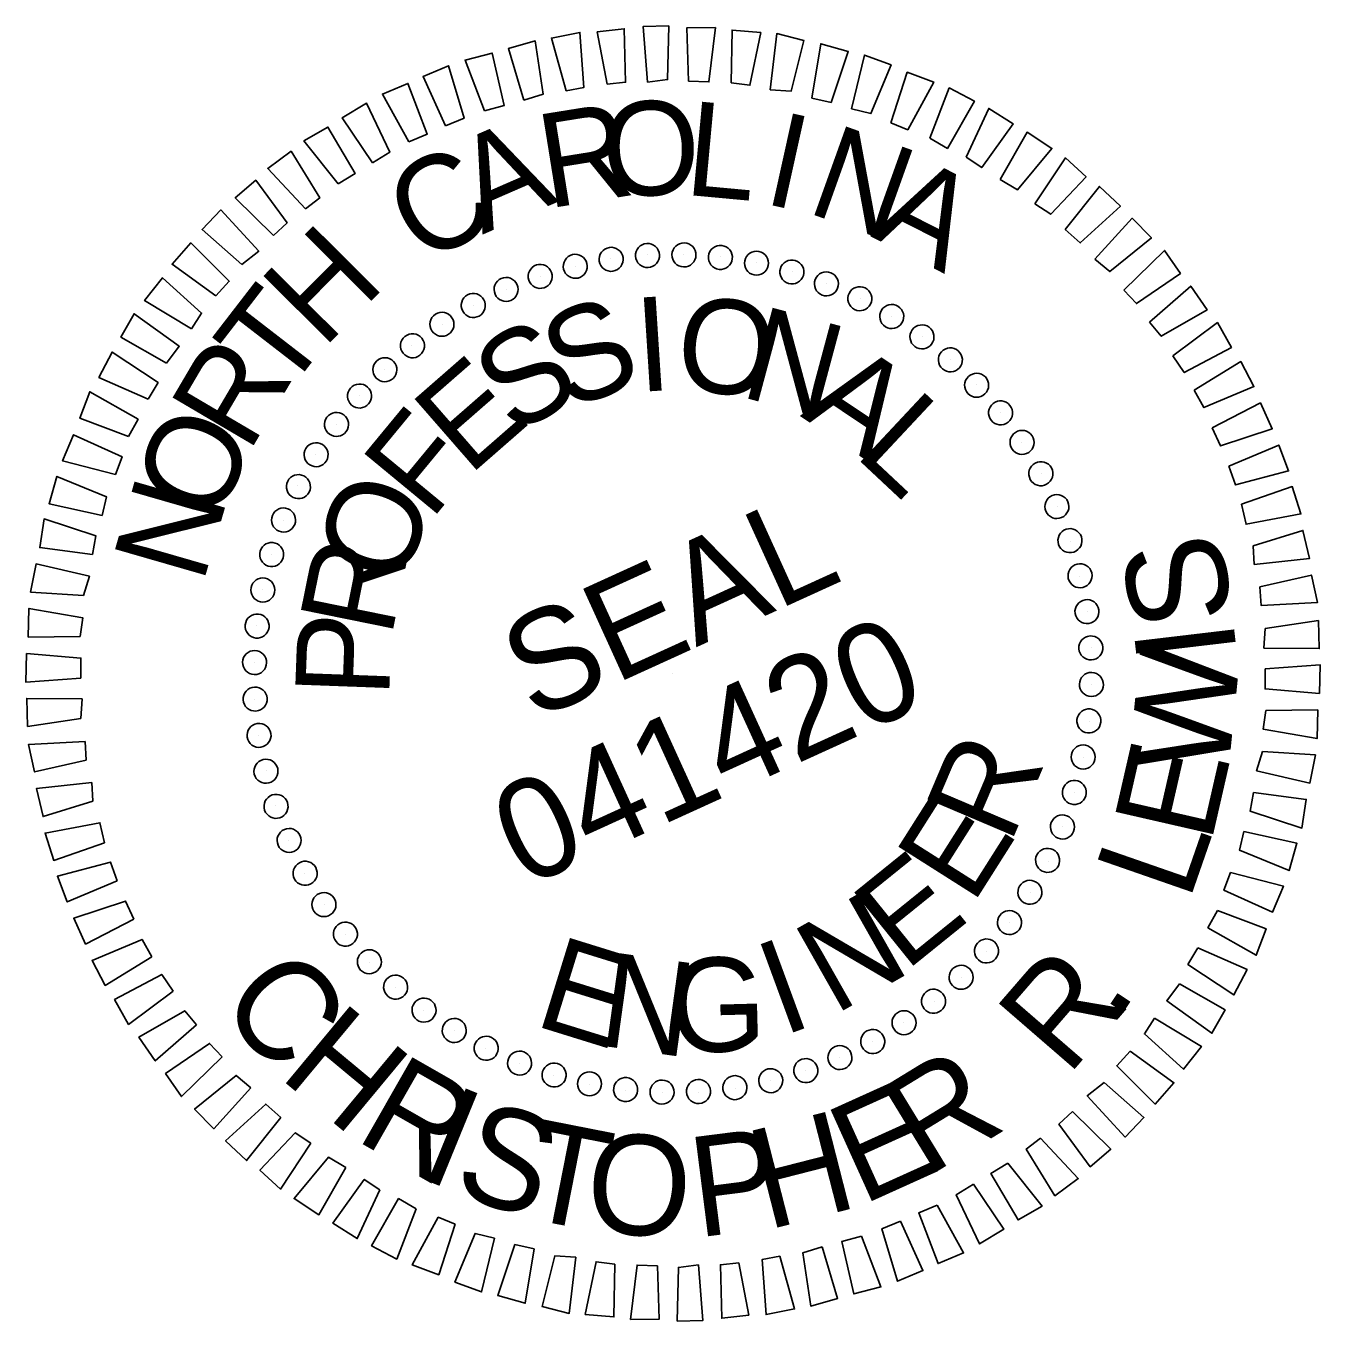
# Model space of a CAD drawing. Extents: x 2246788 to 2248774, y 662010 to 663780.
# Drawn here: x 2248637.9 to 2248715.4, y 663702.5 to 663780.1 of the extents above; entities that cross this region are included whole.
import ezdxf

# ---------------------------------------------------------------- set-up
doc = ezdxf.new("R2010")
doc.units = 0
doc.layers.add('Sheet PE Seal Cell', color=7, linetype='Continuous')

msp = doc.modelspace()

# ---------------------------------------------------------------- linework, layer by layer
at = {"layer": 'Sheet PE Seal Cell'}
for p, q in [((2248675.104, 663766.359), (2248675.104, 663766.359)), ((2248677.297, 663766.369), (2248677.297, 663766.369)), ((2248679.486, 663766.268), (2248679.486, 663766.268)), ((2248670.805, 663765.664), (2248670.805, 663765.664)), ((2248672.903, 663766.125), (2248672.903, 663766.125)), ((2248681.643, 663765.877), (2248681.643, 663765.877)), ((2248668.704, 663765.091), (2248668.704, 663765.091)), ((2248683.795, 663765.374), (2248683.795, 663765.374)), ((2248685.827, 663764.652), (2248685.827, 663764.652)), ((2248666.64, 663764.315), (2248666.64, 663764.315)), ((2248664.658, 663763.357), (2248664.658, 663763.357)), ((2248687.876, 663763.772), (2248687.876, 663763.772)), ((2248689.74, 663762.698), (2248689.74, 663762.698)), ((2248662.826, 663762.193), (2248662.826, 663762.193)), ((2248660.99, 663760.916), (2248660.99, 663760.916)), ((2248691.574, 663761.446), (2248691.574, 663761.446)), ((2248693.292, 663760.086), (2248693.292, 663760.086)), ((2248659.328, 663759.5), (2248659.328, 663759.5)), ((2248694.85, 663758.598), (2248694.85, 663758.598)), ((2248657.84, 663757.942), (2248657.84, 663757.942)), ((2248696.267, 663756.936), (2248696.267, 663756.936)), ((2248656.48, 663756.224), (2248656.48, 663756.224)), ((2248697.543, 663755.1), (2248697.543, 663755.1)), ((2248655.228, 663754.39), (2248655.228, 663754.39)), ((2248698.707, 663753.268), (2248698.707, 663753.268)), ((2248654.154, 663752.526), (2248654.154, 663752.526)), ((2248699.665, 663751.286), (2248699.665, 663751.286)), ((2248653.274, 663750.477), (2248653.274, 663750.477)), ((2248700.441, 663749.222), (2248700.441, 663749.222)), ((2248652.552, 663748.445), (2248652.552, 663748.445)), ((2248701.014, 663747.121), (2248701.014, 663747.121)), ((2248652.049, 663746.293), (2248652.049, 663746.293)), ((2248701.475, 663745.023), (2248701.475, 663745.023)), ((2248651.658, 663744.136), (2248651.658, 663744.136)), ((2248701.709, 663742.822), (2248701.709, 663742.822)), ((2248651.557, 663741.947), (2248651.557, 663741.947)), ((2248676.638, 663741.288), (2248676.638, 663741.288)), ((2248701.719, 663740.629), (2248701.719, 663740.629)), ((2248651.567, 663739.754), (2248651.567, 663739.754)), ((2248701.618, 663738.44), (2248701.618, 663738.44)), ((2248651.801, 663737.553), (2248651.801, 663737.553)), ((2248701.227, 663736.283), (2248701.227, 663736.283)), ((2248652.262, 663735.455), (2248652.262, 663735.455)), ((2248700.724, 663734.131), (2248700.724, 663734.131)), ((2248652.835, 663733.354), (2248652.835, 663733.354)), ((2248700.002, 663732.099), (2248700.002, 663732.099)), ((2248653.611, 663731.289), (2248653.611, 663731.289)), ((2248699.122, 663730.05), (2248699.122, 663730.05)), ((2248654.569, 663729.308), (2248654.569, 663729.308)), ((2248698.048, 663728.186), (2248698.048, 663728.186)), ((2248655.733, 663727.476), (2248655.733, 663727.476)), ((2248696.796, 663726.352), (2248696.796, 663726.352)), ((2248657.01, 663725.64), (2248657.01, 663725.64)), ((2248695.436, 663724.634), (2248695.436, 663724.634)), ((2248658.426, 663723.978), (2248658.426, 663723.978)), ((2248693.948, 663723.076), (2248693.948, 663723.076)), ((2248659.984, 663722.49), (2248659.984, 663722.49)), ((2248692.286, 663721.659), (2248692.286, 663721.659)), ((2248661.702, 663721.13), (2248661.702, 663721.13)), ((2248663.537, 663719.878), (2248663.537, 663719.878)), ((2248690.45, 663720.383), (2248690.45, 663720.383)), ((2248688.618, 663719.219), (2248688.618, 663719.219)), ((2248665.4, 663718.804), (2248665.4, 663718.804)), ((2248686.637, 663718.261), (2248686.637, 663718.261)), ((2248667.449, 663717.924), (2248667.449, 663717.924)), ((2248684.572, 663717.485), (2248684.572, 663717.485)), ((2248669.481, 663717.202), (2248669.481, 663717.202)), ((2248671.634, 663716.699), (2248671.634, 663716.699)), ((2248682.471, 663716.912), (2248682.471, 663716.912)), ((2248673.79, 663716.308), (2248673.79, 663716.308)), ((2248675.979, 663716.207), (2248675.979, 663716.207)), ((2248678.172, 663716.217), (2248678.172, 663716.217)), ((2248680.373, 663716.451), (2248680.373, 663716.451))]:
    msp.add_line(p, q, dxfattribs=at)
for points in [[(2248670.245, 663776.178), (2248669.352, 663779.343), (2248671.065, 663779.684), (2248671.304, 663776.386)], [(2248672.699, 663776.582), (2248672.096, 663779.714), (2248673.713, 663779.901), (2248673.799, 663776.699)], [(2248675.119, 663776.696), (2248674.859, 663780.039), (2248676.382, 663780.074), (2248676.311, 663776.854)], [(2248677.561, 663776.764), (2248677.475, 663779.967), (2248679.175, 663779.973), (2248678.79, 663776.72)], [(2248680.13, 663776.671), (2248680.177, 663779.825), (2248681.894, 663779.673), (2248681.244, 663776.519)], [(2248682.465, 663776.252), (2248682.855, 663779.616), (2248684.473, 663779.2), (2248683.714, 663776.162)], [(2248667.697, 663775.621), (2248666.779, 663778.72), (2248668.384, 663779.176), (2248668.851, 663775.982)], [(2248684.952, 663775.737), (2248685.495, 663779.006), (2248687.134, 663778.544), (2248686.107, 663775.494)], [(2248665.347, 663774.99), (2248664.181, 663778.03), (2248665.807, 663778.441), (2248666.522, 663775.305)], [(2248687.324, 663775.114), (2248688.111, 663778.33), (2248689.701, 663777.736), (2248688.499, 663774.825)], [(2248663.01, 663774.09), (2248661.662, 663777.047), (2248663.184, 663777.686), (2248664.122, 663774.542)], [(2248689.687, 663774.268), (2248690.669, 663777.298), (2248692.259, 663776.704), (2248690.702, 663773.851)], [(2248660.805, 663773.14), (2248659.23, 663775.994), (2248660.752, 663776.632), (2248661.918, 663773.592)], [(2248692.026, 663773.356), (2248693.186, 663776.357), (2248694.701, 663775.564), (2248693.078, 663772.736)], [(2248658.634, 663771.876), (2248656.806, 663774.56), (2248658.27, 663775.447), (2248659.663, 663772.51)], [(2248694.2, 663772.203), (2248695.558, 663775.13), (2248697.024, 663774.205), (2248695.14, 663771.588)], [(2248656.574, 663770.608), (2248654.519, 663773.188), (2248655.958, 663774.009), (2248657.604, 663771.242)], [(2248696.233, 663770.877), (2248697.856, 663773.705), (2248699.343, 663772.734), (2248697.284, 663770.257)], [(2248654.618, 663769.112), (2248652.357, 663771.543), (2248653.758, 663772.566), (2248655.47, 663769.775)], [(2248698.328, 663769.414), (2248700.15, 663772.167), (2248701.384, 663771.027), (2248699.268, 663768.798)], [(2248652.704, 663767.525), (2248650.413, 663769.778), (2248651.637, 663770.831), (2248653.514, 663768.279)], [(2248700.129, 663767.872), (2248702.192, 663770.46), (2248703.447, 663769.274), (2248701.041, 663767.079)], [(2248650.806, 663765.781), (2248648.421, 663767.881), (2248649.537, 663769.049), (2248651.819, 663766.573)], [(2248701.923, 663766.107), (2248704.159, 663768.555), (2248705.302, 663767.372), (2248702.813, 663765.359)], [(2248649.24, 663763.914), (2248646.623, 663765.798), (2248647.743, 663767.078), (2248650.054, 663764.779)], [(2248703.646, 663764.255), (2248706.081, 663766.628), (2248707.038, 663765.251), (2248704.4, 663763.444)], [(2248647.781, 663761.93), (2248644.978, 663763.62), (2248646.056, 663764.991), (2248648.396, 663762.87)], [(2248705.187, 663762.32), (2248707.66, 663764.49), (2248708.638, 663763.068), (2248705.896, 663761.488)], [(2248646.297, 663759.881), (2248643.556, 663761.434), (2248644.345, 663762.837), (2248647.049, 663760.883)], [(2248706.592, 663760.322), (2248709.259, 663762.307), (2248710.1, 663760.822), (2248707.271, 663759.313)], [(2248645.19, 663757.728), (2248642.238, 663759.02), (2248643.032, 663760.535), (2248645.785, 663758.713)], [(2248707.86, 663758.263), (2248710.652, 663759.974), (2248711.448, 663758.469), (2248708.449, 663757.212)], [(2248644.013, 663755.488), (2248641.099, 663756.578), (2248641.693, 663758.167), (2248644.587, 663756.519)], [(2248708.942, 663756.008), (2248711.837, 663757.493), (2248712.542, 663755.946), (2248709.44, 663754.916)], [(2248643.237, 663753.211), (2248640.067, 663754.019), (2248640.727, 663755.584), (2248643.633, 663754.271)], [(2248709.933, 663753.713), (2248712.932, 663754.969), (2248713.525, 663753.426), (2248710.34, 663752.579)], [(2248642.432, 663750.757), (2248639.258, 663751.453), (2248639.72, 663753.092), (2248642.696, 663751.866)], [(2248710.701, 663751.425), (2248713.737, 663752.479), (2248714.26, 663750.849), (2248710.971, 663750.23)], [(2248641.855, 663748.406), (2248638.693, 663748.833), (2248638.957, 663750.546), (2248642.053, 663749.54)], [(2248711.394, 663748.939), (2248714.381, 663749.86), (2248714.768, 663748.168), (2248711.466, 663747.818)], [(2248641.32, 663745.964), (2248638.15, 663746.168), (2248638.479, 663747.856), (2248641.674, 663747.114)], [(2248711.798, 663746.485), (2248714.889, 663747.179), (2248715.254, 663745.533), (2248711.87, 663745.364)], [(2248641.119, 663743.51), (2248638.007, 663743.465), (2248638.047, 663745.187), (2248641.271, 663744.623)], [(2248712.111, 663743.99), (2248715.305, 663744.457), (2248715.356, 663742.777), (2248712.046, 663742.807)], [(2248641.163, 663741.002), (2248637.865, 663740.763), (2248637.905, 663742.485), (2248641.162, 663742.21)], [(2248712.113, 663741.574), (2248715.411, 663741.813), (2248715.371, 663740.091), (2248712.114, 663740.366)], [(2248641.165, 663738.586), (2248637.971, 663738.119), (2248637.92, 663739.799), (2248641.23, 663739.769)], [(2248712.157, 663739.066), (2248715.269, 663739.111), (2248715.229, 663737.389), (2248712.005, 663737.953)], [(2248641.478, 663736.091), (2248638.388, 663735.397), (2248638.022, 663737.043), (2248641.407, 663737.212)], [(2248711.956, 663736.612), (2248715.126, 663736.408), (2248714.797, 663734.72), (2248711.602, 663735.461)], [(2248641.882, 663733.637), (2248638.895, 663732.716), (2248638.508, 663734.408), (2248641.81, 663734.758)], [(2248711.421, 663734.17), (2248714.583, 663733.743), (2248714.319, 663732.029), (2248711.223, 663733.036)], [(2248642.575, 663731.151), (2248639.539, 663730.097), (2248639.016, 663731.727), (2248642.305, 663732.346)], [(2248710.844, 663731.819), (2248714.018, 663731.123), (2248713.556, 663729.484), (2248710.58, 663730.71)], [(2248643.343, 663728.863), (2248640.344, 663727.607), (2248639.751, 663729.149), (2248642.936, 663729.997)], [(2248710.039, 663729.365), (2248713.21, 663728.557), (2248712.549, 663726.992), (2248709.643, 663728.305)], [(2248644.334, 663726.568), (2248641.439, 663725.083), (2248640.734, 663726.63), (2248643.836, 663727.66)], [(2248709.263, 663727.088), (2248712.177, 663725.998), (2248711.583, 663724.409), (2248708.689, 663726.057)], [(2248645.416, 663724.313), (2248642.625, 663722.602), (2248641.829, 663724.107), (2248644.827, 663725.364)], [(2248708.086, 663724.848), (2248711.038, 663723.556), (2248710.245, 663722.041), (2248707.491, 663723.863)], [(2248646.684, 663722.254), (2248644.017, 663720.269), (2248643.176, 663721.754), (2248646.005, 663723.263)], [(2248706.979, 663722.695), (2248709.72, 663721.142), (2248708.931, 663719.739), (2248706.227, 663721.693)], [(2248648.089, 663720.256), (2248645.616, 663718.086), (2248644.639, 663719.508), (2248647.381, 663721.088)], [(2248705.495, 663720.646), (2248708.298, 663718.956), (2248707.22, 663717.585), (2248704.88, 663719.706)], [(2248649.63, 663718.321), (2248647.195, 663715.948), (2248646.238, 663717.325), (2248648.876, 663719.132)], [(2248704.037, 663718.662), (2248706.654, 663716.778), (2248705.533, 663715.498), (2248703.222, 663717.797)], [(2248651.353, 663716.469), (2248649.117, 663714.021), (2248647.974, 663715.204), (2248650.463, 663717.217)], [(2248702.47, 663716.794), (2248704.856, 663714.695), (2248703.739, 663713.527), (2248701.457, 663716.003)], [(2248653.147, 663714.704), (2248651.084, 663712.116), (2248649.829, 663713.302), (2248652.236, 663715.497)], [(2248700.572, 663715.051), (2248702.863, 663712.798), (2248701.639, 663711.745), (2248699.762, 663714.297)], [(2248654.948, 663713.162), (2248653.126, 663710.409), (2248651.892, 663711.549), (2248654.008, 663713.778)], [(2248698.658, 663713.464), (2248700.92, 663711.033), (2248699.518, 663710.009), (2248697.806, 663712.801)], [(2248657.043, 663711.699), (2248655.42, 663708.871), (2248653.933, 663709.842), (2248655.992, 663712.319)], [(2248696.702, 663711.968), (2248698.757, 663709.388), (2248697.318, 663708.567), (2248695.672, 663711.334)], [(2248659.076, 663710.373), (2248657.718, 663707.446), (2248656.252, 663708.371), (2248658.137, 663710.988)], [(2248694.642, 663710.7), (2248696.47, 663708.016), (2248695.006, 663707.129), (2248693.613, 663710.066)], [(2248661.25, 663709.22), (2248660.09, 663706.219), (2248658.575, 663707.012), (2248660.198, 663709.84)], [(2248692.471, 663709.436), (2248694.046, 663706.582), (2248692.524, 663705.943), (2248691.359, 663708.984)], [(2248663.589, 663708.308), (2248662.607, 663705.278), (2248661.017, 663705.872), (2248662.575, 663708.725)], [(2248690.267, 663708.486), (2248691.614, 663705.529), (2248690.092, 663704.89), (2248689.154, 663708.034)], [(2248665.952, 663707.462), (2248665.165, 663704.246), (2248663.576, 663704.84), (2248664.777, 663707.75)], [(2248687.929, 663707.586), (2248689.095, 663704.546), (2248687.469, 663704.135), (2248686.755, 663707.27)], [(2248668.324, 663706.839), (2248667.781, 663703.57), (2248666.142, 663704.032), (2248667.169, 663707.082)], [(2248685.58, 663706.955), (2248686.497, 663703.856), (2248684.892, 663703.4), (2248684.425, 663706.594)], [(2248670.812, 663706.324), (2248670.422, 663702.96), (2248668.803, 663703.376), (2248669.562, 663706.414)], [(2248673.146, 663705.905), (2248673.099, 663702.751), (2248671.382, 663702.903), (2248672.033, 663706.057)], [(2248675.716, 663705.812), (2248675.801, 663702.609), (2248674.101, 663702.603), (2248674.487, 663705.856)], [(2248678.157, 663705.88), (2248678.417, 663702.537), (2248676.894, 663702.502), (2248676.965, 663705.722)], [(2248680.578, 663705.994), (2248681.181, 663702.862), (2248679.563, 663702.675), (2248679.477, 663705.877)], [(2248683.031, 663706.398), (2248683.924, 663703.233), (2248682.211, 663702.892), (2248681.972, 663706.19)]]:
    msp.add_lwpolyline(points, close=True, dxfattribs=at)
for centre, major_axis in [((2248675.108, 663766.321), (-0.044, 0.719)), ((2248677.295, 663766.359), (0.019, 0.72)), ((2248679.478, 663766.207), (0.082, 0.715)), ((2248670.784, 663765.675), (-0.168, 0.7)), ((2248672.932, 663766.093), (-0.106, 0.712)), ((2248681.639, 663765.864), (0.144, 0.706)), ((2248668.681, 663765.072), (-0.228, 0.683)), ((2248683.762, 663765.335), (0.205, 0.69)), ((2248685.831, 663764.623), (0.264, 0.67)), ((2248666.638, 663764.288), (-0.287, 0.66)), ((2248664.672, 663763.329), (-0.344, 0.633)), ((2248687.83, 663763.733), (0.321, 0.644)), ((2248689.743, 663762.672), (0.376, 0.614)), ((2248662.796, 663762.202), (-0.397, 0.6)), ((2248661.026, 663760.916), (-0.448, 0.563)), ((2248691.557, 663761.448), (0.428, 0.579)), ((2248693.257, 663760.071), (0.477, 0.539)), ((2248659.375, 663759.481), (-0.496, 0.522)), ((2248694.831, 663758.551), (0.522, 0.496)), ((2248657.855, 663757.907), (-0.539, 0.477)), ((2248696.266, 663756.9), (0.563, 0.448)), ((2248656.478, 663756.207), (-0.579, 0.428)), ((2248697.552, 663755.13), (0.6, 0.397)), ((2248655.254, 663754.393), (-0.614, 0.376)), ((2248698.679, 663753.254), (0.633, 0.344)), ((2248654.194, 663752.479), (-0.644, 0.321)), ((2248699.638, 663751.288), (0.66, 0.287)), ((2248653.304, 663750.481), (-0.67, 0.264)), ((2248700.422, 663749.245), (0.683, 0.228)), ((2248652.591, 663748.412), (-0.69, 0.205)), ((2248701.025, 663747.142), (0.7, 0.168)), ((2248652.062, 663746.289), (-0.706, 0.144)), ((2248701.443, 663744.994), (0.712, 0.106)), ((2248651.719, 663744.128), (-0.715, 0.082)), ((2248701.671, 663742.818), (0.719, 0.044)), ((2248651.567, 663741.945), (-0.72, 0.019)), ((2248701.709, 663740.631), (0.72, -0.019)), ((2248651.605, 663739.758), (-0.719, -0.044)), ((2248701.557, 663738.448), (0.715, -0.082)), ((2248651.833, 663737.582), (-0.712, -0.106)), ((2248701.214, 663736.287), (0.706, -0.144)), ((2248652.251, 663735.434), (-0.7, -0.168)), ((2248700.685, 663734.164), (0.69, -0.205)), ((2248652.854, 663733.331), (-0.683, -0.228)), ((2248699.973, 663732.095), (0.67, -0.264)), ((2248653.638, 663731.288), (-0.66, -0.287)), ((2248699.083, 663730.097), (0.644, -0.321)), ((2248654.597, 663729.322), (-0.633, -0.344)), ((2248698.022, 663728.183), (0.614, -0.376)), ((2248655.724, 663727.446), (-0.6, -0.397)), ((2248696.798, 663726.369), (0.579, -0.428)), ((2248657.01, 663725.676), (-0.563, -0.448)), ((2248695.421, 663724.669), (0.539, -0.477)), ((2248658.445, 663724.025), (-0.522, -0.496)), ((2248693.901, 663723.095), (0.496, -0.522)), ((2248660.019, 663722.505), (-0.477, -0.539)), ((2248692.25, 663721.66), (0.448, -0.563)), ((2248661.719, 663721.128), (-0.428, -0.579)), ((2248663.533, 663719.904), (-0.376, -0.614)), ((2248690.48, 663720.374), (0.397, -0.6)), ((2248665.447, 663718.843), (-0.321, -0.644)), ((2248688.604, 663719.247), (0.344, -0.633)), ((2248686.638, 663718.288), (0.287, -0.66)), ((2248667.445, 663717.953), (-0.264, -0.67)), ((2248684.595, 663717.504), (0.228, -0.683)), ((2248669.514, 663717.241), (-0.205, -0.69)), ((2248671.637, 663716.712), (-0.144, -0.706)), ((2248682.492, 663716.901), (0.168, -0.7)), ((2248673.798, 663716.369), (-0.082, -0.715)), ((2248675.981, 663716.217), (-0.019, -0.72)), ((2248678.168, 663716.255), (0.044, -0.719)), ((2248680.344, 663716.483), (0.106, -0.712))]:
    msp.add_ellipse(centre, major_axis=major_axis, ratio=0.999708, dxfattribs=at)

# ---------------------------------------------------------------- texts
for s, height, rotation, p in [('O', 5.638, 1.91911, (2248672.477, 663769.832)), ('L', 5.638, 354.71882, (2248677.248, 663769.973)), ('R', 5.638, 9.11904, (2248669.118, 663769.126)), ('I', 5.638, 347.51808, (2248681.929, 663769.469)), ('N', 5.639, 340.31685, (2248684.528, 663768.95)), ('A', 5.638, 23.51826, (2248665.213, 663767.566)), ('C', 5.638, 30.71781, (2248661.743, 663765.655)), ('A', 5.639, 333.1151, (2248688.436, 663767.489)), ('H', 5.638, 45.11742, (2248655.657, 663760.684)), ('T', 5.638, 52.31772, (2248653.383, 663757.835)), ('I', 5.638, 3.68755, (2248674.561, 663758.144)), ('O', 5.638, 354.33143, (2248676.672, 663758.337)), ('S', 5.638, 22.39834, (2248670.358, 663756.998)), ('N', 5.639, 344.97455, (2248680.549, 663757.906)), ('S', 5.638, 31.75355, (2248667.103, 663755.46)), ('R', 5.639, 59.51845, (2248651.202, 663754.423)), ('E', 5.638, 41.10901, (2248664.399, 663753.074)), ('A', 5.639, 326.25821, (2248684.221, 663756.722)), ('L', 5.639, 316.89879, (2248687.426, 663754.391)), ('F', 5.638, 50.46498, (2248662.109, 663750.382)), ('O', 5.639, 66.71968, (2248649.348, 663750.171)), ('N', 5.639, 73.92144, (2248648.457, 663746.579)), ('O', 5.639, 69.17918, (2248660.329, 663746.329)), ('SEAL', 5.9982, 24.49794, (2248668.279, 663738.412)), ('S', 5.998, 100.55241, (2248710.285, 663744.689)), ('R', 5.639, 78.53759, (2248659.753, 663743.374)), ('P', 5.639, 87.89683, (2248659.624, 663739.799)), ('041420', 5.9982, 24.49794, (2248667.729, 663728.428)), ('I', 5.998, 96.75046, (2248710.436, 663742.451)), ('W', 5.998, 84.21639, (2248709.883, 663735.088)), ('R', 5.639, 66.97935, (2248696.829, 663730.983)), ('E', 5.998, 77.10705, (2248708.86, 663731.021)), ('E', 5.638, 57.62203, (2248694.573, 663727.372)), ('L', 5.998, 70.83229, (2248707.545, 663727.561)), ('E', 5.638, 38.9097, (2248690.559, 663723.4)), ('N', 5.638, 29.55433, (2248686.303, 663720.801)), ('E', 5.638, 342.77483, (2248668.204, 663720.246)), ('I', 5.638, 20.19914, (2248683.193, 663719.549)), ('N', 5.639, 352.1319, (2248672.053, 663719.033)), ('G', 5.638, 1.48818, (2248676.444, 663718.562)), ('R', 5.998, 49.11789, (2248700.273, 663717.1)), ('C', 5.998, 310.69992, (2248649.251, 663721.448)), ('.', 5.998, 56.59815, (2248703.221, 663720.383)), ('H', 5.998, 320.28207, (2248652.935, 663717.166)), ('R', 5.998, 330.26605, (2248657.476, 663713.422)), ('R', 5.998, 31.43728, (2248691.811, 663711.065)), ('E', 5.998, 24.32794, (2248687.953, 663709.419)), ('I', 5.998, 337.74631, (2248661.267, 663711.165)), ('S', 5.998, 341.54826, (2248663.298, 663710.212)), ('H', 5.998, 14.34395, (2248682.257, 663707.94)), ('T', 5.998, 348.87397, (2248667.37, 663708.765)), ('O', 5.998, 355.67421, (2248671.286, 663707.896)), ('P', 5.998, 7.23461, (2248678.086, 663707.501))]:
    msp.add_text(s, height=height, rotation=rotation, dxfattribs=at).set_placement(p)

doc.saveas('drawing.dxf')
